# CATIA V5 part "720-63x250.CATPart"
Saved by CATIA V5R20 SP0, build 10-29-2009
Part number: 720-63x250
Definition: NONE
Nomenclature: 720-63x250
Source: Unknown
Description: 720-63x250
Bounding box of the stored display mesh (mm): x 0 to 250, y -31.5 to 31.5, z -31.5 to 31.5
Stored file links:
  C:\Users\Utente\Desktop\IO LAVORO\3D X SITO CF\X SITO\720\720-63x250.CATPart
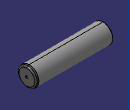
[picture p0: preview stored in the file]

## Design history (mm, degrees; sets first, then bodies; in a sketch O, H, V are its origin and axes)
Body1 "720-63x250" (main body)
  Solid1: solid without history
